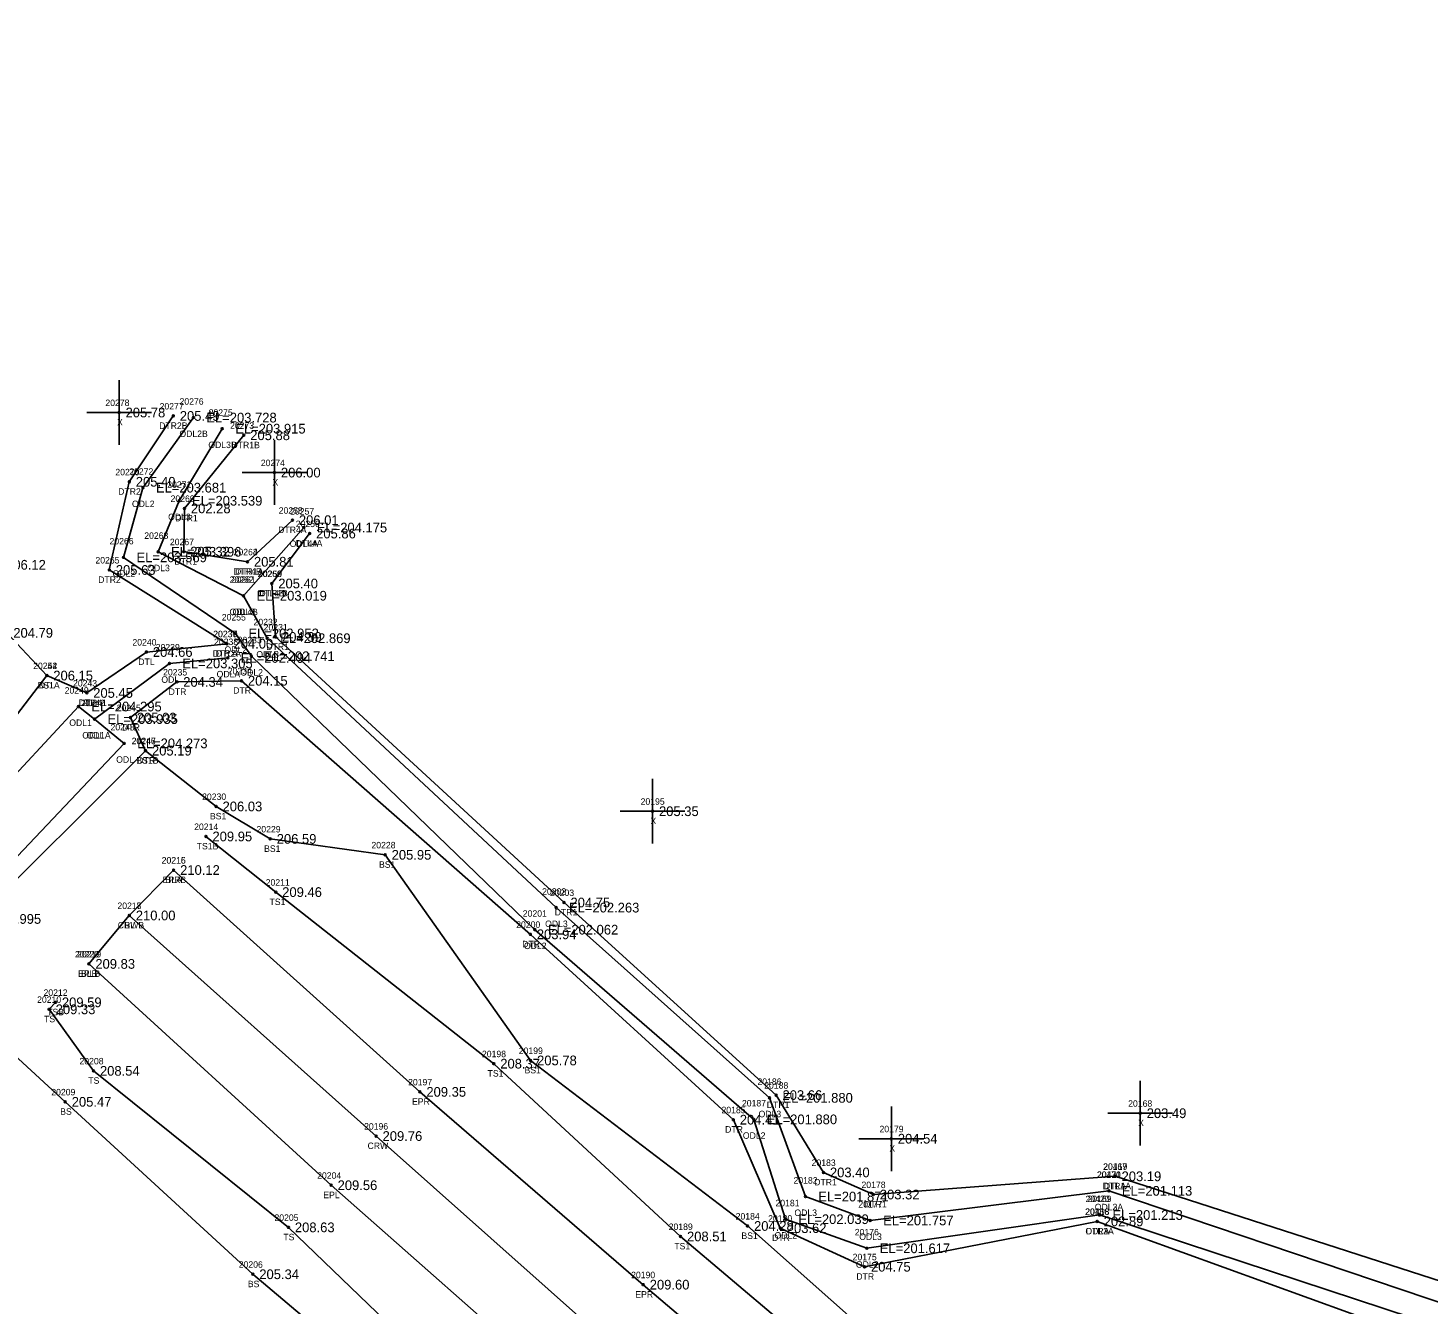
# Model space of a CAD drawing. Extents: x 2260230 to 2261304, y 1064626 to 1065587.
# Drawn here: x 2260481.3 to 2260697.7, y 1065283.6 to 1065480.8 of the extents above; entities that cross this region are included whole.
import ezdxf

# ---------------------------------------------------------------- set-up
doc = ezdxf.new("R2010")
doc.units = 0
for name, color, linetype in [('RD_DTM_BkLn1', 7, 'Continuous'), ('RD_DTM_BkLn2', 7, 'Continuous'), ('RD_DTM_BkLn_txCode', 7, 'Continuous'), ('RD_EX_H2O', 7, 'Continuous'), ('RD_EX_H2O_txCode', 7, 'Continuous'), ('RD_EX_Misc', 7, 'Continuous'), ('RD_EX_Misc_txCode', 7, 'Continuous'), ('RD_EX_Road', 7, 'Continuous'), ('RD_EX_Road_txCode', 7, 'Continuous'), ('RD_EX_TX_H2O_ELEV', 7, 'Continuous'), ('RD_EX_TX_Misc_ELEV', 7, 'Continuous'), ('RD_EX_TX_Road_ELEV', 7, 'Continuous'), ('RD_HC_Survey_ELEV', 7, 'Continuous'), ('RD_HC_Survey_txCode', 7, 'Continuous'), ('RD_SMD_Locator', 7, 'Continuous')]:
    doc.layers.add(name, color=color, linetype=linetype)

msp = doc.modelspace()

# ---------------------------------------------------------------- linework, layer by layer
at = {"layer": 'RD_DTM_BkLn1'}
for points in [[(2260503.82, 1065350.69), (2260496.97, 1065343.67), (2260490.72, 1065336.18)], [(2260779.46, 1065104.44), (2260742.48, 1065135.39), (2260673.31, 1065192.46), (2260608.04, 1065246.07), (2260570.56, 1065278.04), (2260535.11, 1065309.57), (2260496.97, 1065343.67)]]:
    msp.add_lwpolyline(points, dxfattribs=at)
at = {"layer": 'RD_DTM_BkLn2'}
for points in [[(2260484.22, 1065380.75), (2260478.04, 1065387.35), (2260476.93, 1065397.87), (2260411.32, 1065463.45), (2260400.24, 1065480.84)], [(2260803.42, 1065119.58), (2260791.14, 1065121.96), (2260758.99, 1065152.43), (2260688.43, 1065210.53), (2260677.06, 1065221.37), (2260674.34, 1065224.52), (2260669.99, 1065225.64), (2260624.69, 1065267.1), (2260592.52, 1065295.67), (2260558.99, 1065321.26), (2260536.51, 1065353.04), (2260518.75, 1065355.5), (2260510.38, 1065360.52), (2260499.47, 1065369.14)], [(2260788.43, 1065115.1), (2260756.25, 1065149.85), (2260685.54, 1065207.45), (2260620.51, 1065261.6), (2260582.16, 1065294.05), (2260553.3, 1065320.76), (2260519.6, 1065347.28), (2260508.82, 1065355.88)], [(2260769.94, 1065084.22), (2260759.25, 1065090.93), (2260723.51, 1065114.68), (2260656.37, 1065173.06), (2260640.88, 1065186.75), (2260590.19, 1065225.63), (2260553.18, 1065256.82), (2260516.06, 1065288.21), (2260487.07, 1065314.86), (2260465.96, 1065334.21)], [(2260770.13, 1065093.5), (2260766.75, 1065094.76), (2260758.85, 1065096.78), (2260743.23, 1065112.86), (2260730.88, 1065117.95), (2260648.47, 1065190.67), (2260642.26, 1065193.52), (2260595.88, 1065231.39), (2260557.16, 1065261.19), (2260521.56, 1065295.46), (2260491.43, 1065319.65), (2260484.59, 1065329.16), (2260485.55, 1065330.24)]]:
    msp.add_lwpolyline(points, dxfattribs=at)
at = {"layer": 'RD_EX_H2O'}
for p, q in [((2260522.18, 1065404.77), (2260515.23, 1065398.34)), ((2260523.94, 1065403.63), (2260514.62, 1065393.09)), ((2260524.84, 1065402.7), (2260518.99, 1065394.98))]:
    msp.add_line(p, q, dxfattribs=at)
for points in [[(2260512.07, 1065385.67), (2260493.88, 1065397.07), (2260496.97, 1065410.7), (2260503.77, 1065420.88)], [(2260646.91, 1065297.37), (2260610.95, 1065292.22), (2260598.38, 1065296.72), (2260593.48, 1065312.15), (2260559.66, 1065341.47), (2260515.83, 1065383.74), (2260513.38, 1065387.26), (2260496.08, 1065399.02), (2260499.08, 1065409.79), (2260506.87, 1065420.62)], [(2260648.37, 1065301.1), (2260611.48, 1065296.52), (2260601.45, 1065300.22), (2260595.91, 1065315.48), (2260562.92, 1065344.88), (2260518.29, 1065386.52), (2260514.62, 1065393.09), (2260501.42, 1065399.88), (2260504.66, 1065407.77), (2260511.34, 1065418.91)], [(2260515.23, 1065398.34), (2260505.38, 1065399.9), (2260505.49, 1065406.59), (2260514.66, 1065417.89)], [(2260649.32, 1065303.35), (2260611.96, 1065300.53), (2260604.25, 1065303.95), (2260596.92, 1065315.9), (2260564.15, 1065345.67), (2260519.57, 1065386.72), (2260518.99, 1065394.98)], [(2260512.07, 1065385.67), (2260499.61, 1065384.39), (2260490.39, 1065378.06), (2260484.22, 1065380.75), (2260461.06, 1065350.52), (2260459.63, 1065339.19), (2260447.16, 1065331.46), (2260428.77, 1065320.54)], [(2260512.19, 1065383.47), (2260503.16, 1065382.63), (2260491.6, 1065374.02), (2260496.18, 1065370.27), (2260470.47, 1065343.13), (2260465.09, 1065335.21), (2260448.41, 1065329.85), (2260430.6, 1065317.94)], [(2260646.56, 1065296.38), (2260610.59, 1065289.37), (2260597.58, 1065295.34), (2260590.32, 1065312.1), (2260558.95, 1065340.75), (2260514.3, 1065379.95), (2260504.3, 1065379.76), (2260497.13, 1065374.25), (2260499.47, 1065369.14), (2260472.37, 1065342.14), (2260468.09, 1065337.19), (2260465.96, 1065334.21), (2260450.6, 1065327.87), (2260431.86, 1065315.1)], [(2260491.6, 1065374.02), (2260489.1, 1065375.96), (2260466.13, 1065351.23), (2260467.67, 1065345), (2260461.29, 1065337.12), (2260448.41, 1065329.85)], [(2260649.32, 1065303.35), (2260742.36, 1065273.33), (2260794.49, 1065236.41), (2260847.14, 1065213.75), (2260856.6, 1065227.36), (2260843.65, 1065244.12)], [(2260648.37, 1065301.1), (2260738.72, 1065270.62), (2260793.11, 1065233.68), (2260850.51, 1065208.71), (2260885.55, 1065179.82)], [(2260646.91, 1065297.37), (2260734.94, 1065268.39), (2260788.77, 1065229.77), (2260848.02, 1065204.23), (2260881.52, 1065170.81)], [(2260646.56, 1065296.38), (2260731.62, 1065265.57), (2260787.15, 1065228.1), (2260847.76, 1065200.44), (2260874.83, 1065172.21)]]:
    msp.add_lwpolyline(points, dxfattribs=at)
at = {"layer": 'RD_EX_Misc'}
for p, q in [((2260495.39, 1065416.41), (2260495.39, 1065426.41)), ((2260490.39, 1065421.41), (2260500.39, 1065421.41)), ((2260519.4, 1065407.12), (2260519.4, 1065417.12)), ((2260514.4, 1065412.12), (2260524.4, 1065412.12)), ((2260577.83, 1065354.78), (2260577.83, 1065364.78)), ((2260572.83, 1065359.78), (2260582.83, 1065359.78)), ((2260653.2, 1065308.1), (2260653.2, 1065318.1)), ((2260614.74, 1065304.16), (2260614.74, 1065314.16)), ((2260648.2, 1065313.1), (2260658.2, 1065313.1)), ((2260609.74, 1065309.16), (2260619.74, 1065309.16))]:
    msp.add_line(p, q, dxfattribs=at)
at = {"layer": 'RD_EX_Road'}
for points in [[(2260785.94, 1065112.1), (2260748.83, 1065143.25), (2260679.89, 1065200.15), (2260614.93, 1065253.84), (2260576.4, 1065286.6), (2260541.88, 1065316.4), (2260503.82, 1065350.69)], [(2260773.44, 1065097.37), (2260736.13, 1065128.07), (2260602.8, 1065238.77), (2260563.77, 1065270.54), (2260528.16, 1065301.97), (2260490.72, 1065336.18)]]:
    msp.add_lwpolyline(points, dxfattribs=at)
at = {"layer": 'RD_SMD_Locator'}
for centre in [(2260495.39, 1065421.41), (2260503.77, 1065420.88), (2260506.87, 1065420.62), (2260511.34, 1065418.91), (2260514.66, 1065417.89), (2260519.4, 1065412.12), (2260496.97, 1065410.7), (2260499.08, 1065409.79), (2260504.66, 1065407.77), (2260505.49, 1065406.59), (2260522.18, 1065404.77), (2260523.94, 1065403.63), (2260524.84, 1065402.7), (2260496.08, 1065399.02), (2260501.42, 1065399.88), (2260505.38, 1065399.9), (2260515.23, 1065398.34), (2260515.23, 1065398.34), (2260493.88, 1065397.07), (2260518.99, 1065394.98), (2260518.99, 1065394.98), (2260514.62, 1065393.09), (2260514.62, 1065393.09), (2260512.07, 1065385.67), (2260512.07, 1065385.67), (2260513.38, 1065387.26), (2260518.29, 1065386.52), (2260519.57, 1065386.72), (2260499.61, 1065384.39), (2260512.19, 1065383.47), (2260515.83, 1065383.74), (2260503.16, 1065382.63), (2260484.22, 1065380.75), (2260484.22, 1065380.75), (2260504.3, 1065379.76), (2260514.3, 1065379.95), (2260490.39, 1065378.06), (2260489.1, 1065375.96), (2260491.6, 1065374.02), (2260491.6, 1065374.02), (2260497.13, 1065374.25), (2260496.18, 1065370.27), (2260499.47, 1065369.14), (2260499.47, 1065369.14), (2260510.38, 1065360.52), (2260577.83, 1065359.78), (2260508.82, 1065355.88), (2260518.75, 1065355.5), (2260536.51, 1065353.04), (2260503.82, 1065350.69), (2260503.82, 1065350.69), (2260519.6, 1065347.28), (2260562.92, 1065344.88), (2260564.15, 1065345.67), (2260496.97, 1065343.67), (2260496.97, 1065343.67), (2260558.95, 1065340.75), (2260559.66, 1065341.47), (2260490.72, 1065336.18), (2260490.72, 1065336.18), (2260484.59, 1065329.16), (2260485.55, 1065330.24), (2260553.3, 1065320.76), (2260558.99, 1065321.26), (2260491.43, 1065319.65), (2260541.88, 1065316.4), (2260596.92, 1065315.9), (2260487.07, 1065314.86), (2260595.91, 1065315.48), (2260590.32, 1065312.1), (2260593.48, 1065312.15), (2260653.2, 1065313.1), (2260535.11, 1065309.57), (2260614.74, 1065309.16), (2260604.25, 1065303.95), (2260649.32, 1065303.35), (2260649.32, 1065303.35), (2260528.16, 1065301.97), (2260648.37, 1065301.1), (2260648.37, 1065301.1), (2260601.45, 1065300.22), (2260611.96, 1065300.53), (2260598.38, 1065296.72), (2260611.48, 1065296.52), (2260646.91, 1065297.37), (2260646.91, 1065297.37), (2260521.56, 1065295.46), (2260592.52, 1065295.67), (2260597.58, 1065295.34), (2260646.56, 1065296.38), (2260646.56, 1065296.38), (2260582.16, 1065294.05), (2260610.95, 1065292.22), (2260516.06, 1065288.21), (2260610.59, 1065289.37), (2260576.4, 1065286.6)]:
    msp.add_circle(centre, 0.15, dxfattribs=at)

# ---------------------------------------------------------------- texts
at = {"layer": 'RD_DTM_BkLn_txCode'}
for s, p in [('20252', (2260482.11, 1065381.75)), ('BS1A', (2260482.79, 1065378.75)), ('20247', (2260497.35, 1065370.14)), ('BS1B', (2260498.05, 1065367.14)), ('20230', (2260508.22, 1065361.52)), ('BS1', (2260509.43, 1065358.52)), ('20214', (2260506.99, 1065356.88)), ('20229', (2260516.63, 1065356.5)), ('20228', (2260534.39, 1065354.04)), ('TS1B', (2260507.39, 1065353.88)), ('BS1', (2260517.8, 1065353.5)), ('20216', (2260501.96, 1065351.69)), ('BS1', (2260535.56, 1065351.04)), ('BLA', (2260502.57, 1065348.69)), ('20211', (2260518.05, 1065348.28)), ('20217', (2260495.13, 1065344.67)), ('TS1', (2260518.64, 1065345.28)), ('BL', (2260496.21, 1065341.67)), ('20219', (2260488.89, 1065337.18)), ('BLB', (2260489.5, 1065334.18)), ('20212', (2260483.71, 1065331.24)), ('20210', (2260482.72, 1065330.16)), ('TSB', (2260484.28, 1065328.24)), ('TS', (2260483.8, 1065327.16)), ('20198', (2260551.47, 1065321.76)), ('20199', (2260557.16, 1065322.26)), ('20208', (2260489.27, 1065320.65)), ('TS', (2260490.63, 1065317.65)), ('TS1', (2260552.34, 1065318.76)), ('BS1', (2260558.05, 1065319.26)), ('20209', (2260484.91, 1065315.86)), ('BS', (2260486.29, 1065312.86)), ('20205', (2260519.4, 1065296.46)), ('20184', (2260590.68, 1065296.67)), ('TS', (2260520.77, 1065293.46)), ('20189', (2260580.33, 1065295.05)), ('BS1', (2260591.57, 1065293.67)), ('TS1', (2260581.2, 1065292.05)), ('20206', (2260513.88, 1065289.21)), ('BS', (2260515.28, 1065286.21))]:
    msp.add_text(s, height=1, dxfattribs=at).set_placement(p)
at = {"layer": 'RD_EX_H2O_txCode'}
for s, p in [('20277', (2260501.65, 1065421.88)), ('20276', (2260504.73, 1065422.62)), ('20275', (2260509.23, 1065420.91)), ('DTR2B', (2260501.58, 1065418.88)), ('ODL2B', (2260504.71, 1065417.62)), ('20273', (2260512.54, 1065418.89)), ('ODL3B', (2260509.18, 1065415.91)), ('DTR1B', (2260512.76, 1065415.89)), ('20270', (2260494.81, 1065411.7)), ('20272', (2260496.96, 1065411.79)), ('DTR2', (2260495.25, 1065408.7)), ('20271', (2260502.83, 1065409.77)), ('ODL2', (2260497.38, 1065406.79)), ('20269', (2260503.35, 1065407.59)), ('ODL3', (2260502.97, 1065404.77)), ('DTR1', (2260504.06, 1065404.59)), ('20258', (2260520.06, 1065405.77)), ('20257', (2260521.82, 1065405.63)), ('20268', (2260499.28, 1065401.88)), ('DTR4A', (2260519.98, 1065402.77)), ('20256', (2260522.69, 1065403.7)), ('20266', (2260493.91, 1065401.02)), ('20267', (2260503.24, 1065400.9)), ('ODL4A', (2260521.76, 1065400.63)), ('DTL4A', (2260522.65, 1065400.7)), ('20265', (2260491.73, 1065398.07)), ('DTR1', (2260503.94, 1065397.9)), ('20263', (2260513.09, 1065399.34)), ('20264', (2260513.09, 1065399.34)), ('ODL2', (2260494.38, 1065396.02)), ('ODL3', (2260499.73, 1065396.88)), ('20262', (2260512.48, 1065395.09)), ('20261', (2260512.76, 1065395.09)), ('DTR4B', (2260513.04, 1065396.34)), ('DTR1A', (2260513.31, 1065396.34)), ('20260', (2260516.81, 1065395.98)), ('20259', (2260516.87, 1065395.98)), ('DTR2', (2260492.16, 1065395.07)), ('DTL4B', (2260516.82, 1065392.98)), ('DTR1B', (2260517.08, 1065392.98)), ('20255', (2260511.26, 1065389.26)), ('ODL4B', (2260512.46, 1065390.09)), ('ODL3', (2260512.93, 1065390.09)), ('20236', (2260509.92, 1065386.67)), ('20237', (2260509.95, 1065386.67)), ('20232', (2260516.17, 1065388.52)), ('20231', (2260517.73, 1065387.72)), ('20240', (2260497.45, 1065385.39)), ('20239', (2260501.05, 1065384.63)), ('20238', (2260510.07, 1065385.47)), ('20233', (2260513.71, 1065385.74)), ('DTR1', (2260518.14, 1065384.72)), ('DTL', (2260498.36, 1065382.39)), ('DTR2A', (2260509.86, 1065383.67)), ('DTLA', (2260510.33, 1065383.67)), ('ODL2', (2260511.68, 1065384.26)), ('ODL3', (2260516.6, 1065383.52)), ('20244', (2260482.11, 1065381.75)), ('20235', (2260502.19, 1065380.76)), ('ODLA', (2260510.46, 1065380.47)), ('20234', (2260512.18, 1065380.95)), ('ODL2', (2260514.13, 1065380.74)), ('DTL', (2260482.98, 1065378.75)), ('20249', (2260486.98, 1065377.96)), ('20243', (2260488.27, 1065379.06)), ('ODL', (2260501.92, 1065379.63)), ('DTR', (2260513.03, 1065377.95)), ('DTL', (2260489.15, 1065376.06)), ('20242', (2260489.48, 1065376.02)), ('20241', (2260489.77, 1065376.02)), ('DTR', (2260503.04, 1065377.76)), ('20245', (2260495.01, 1065375.25)), ('ODL1', (2260487.69, 1065372.96)), ('20248', (2260494.07, 1065372.27)), ('DTR', (2260495.86, 1065372.25)), ('ODL1A', (2260489.7, 1065371.02)), ('ODL', (2260490.36, 1065371.02)), ('20246', (2260497.32, 1065370.14)), ('ODL', (2260494.94, 1065367.27)), ('DTR', (2260498.2, 1065367.14)), ('20202', (2260560.77, 1065346.88)), ('20203', (2260561.99, 1065346.67)), ('20201', (2260557.78, 1065343.47)), ('DTR1', (2260562.71, 1065343.67)), ('20200', (2260556.76, 1065341.75)), ('ODL3', (2260561.23, 1065341.88)), ('DTR', (2260557.69, 1065338.75)), ('ODL2', (2260557.96, 1065338.47)), ('20186', (2260594.05, 1065317.48)), ('20188', (2260595.09, 1065316.9)), ('20185', (2260588.49, 1065313.1)), ('20187', (2260591.65, 1065314.15)), ('DTR1', (2260595.49, 1065313.9)), ('ODL3', (2260594.22, 1065312.48)), ('DTR', (2260589.05, 1065310.1)), ('ODL2', (2260591.79, 1065309.15)), ('20183', (2260602.42, 1065304.95)), ('20167', (2260647.46, 1065304.35)), ('20419', (2260647.49, 1065304.35)), ('20182', (2260599.62, 1065302.22)), ('20170', (2260646.49, 1065303.1)), ('20421', (2260646.53, 1065303.1)), ('DTR1', (2260602.82, 1065301.95)), ('20178', (2260610.13, 1065301.53)), ('DTR1A', (2260647.4, 1065301.35)), ('DTLA', (2260647.59, 1065301.35)), ('20181', (2260596.83, 1065298.72)), ('20177', (2260609.64, 1065298.52)), ('DTR1', (2260610.53, 1065298.53)), ('20420', (2260644.76, 1065299.37)), ('20169', (2260645.05, 1065299.37)), ('ODL3A', (2260646.18, 1065298.1)), ('ODL2A', (2260646.18, 1065298.1)), ('20180', (2260595.7, 1065296.34)), ('ODL3', (2260599.76, 1065297.22)), ('20166', (2260644.67, 1065297.38)), ('20418', (2260644.72, 1065297.38)), ('ODL2', (2260596.69, 1065293.72)), ('20176', (2260609.09, 1065294.22)), ('ODL3', (2260609.78, 1065293.52)), ('ODL2A', (2260644.73, 1065294.37)), ('ODL3A', (2260644.73, 1065294.37)), ('DTRA', (2260644.8, 1065294.38)), ('DTRA', (2260644.8, 1065294.38)), ('DTR', (2260596.31, 1065293.34)), ('20175', (2260608.76, 1065290.37)), ('ODL2', (2260609.26, 1065289.22)), ('DTR', (2260609.33, 1065287.37))]:
    msp.add_text(s, height=1, dxfattribs=at).set_placement(p)
at = {"layer": 'RD_EX_Misc_txCode'}
for s, p in [('20278', (2260493.27, 1065422.41)), ('X', (2260495.08, 1065419.41)), ('20274', (2260517.29, 1065413.12)), ('X', (2260519.09, 1065410.12)), ('20195', (2260575.99, 1065360.78)), ('X', (2260577.51, 1065357.78)), ('20168', (2260651.34, 1065314.1)), ('X', (2260652.88, 1065311.1)), ('20179', (2260612.91, 1065310.16)), ('X', (2260614.43, 1065307.16))]:
    msp.add_text(s, height=1, dxfattribs=at).set_placement(p)
at = {"layer": 'RD_EX_Road_txCode'}
for s, p in [('20215', (2260501.98, 1065351.69)), ('EPRB', (2260502.12, 1065348.69)), ('20220', (2260488.57, 1065337.18)), ('EPLB', (2260489.05, 1065334.18)), ('20197', (2260540.05, 1065317.4)), ('EPR', (2260540.66, 1065314.4)), ('20204', (2260526, 1065302.97)), ('EPL', (2260526.95, 1065299.97)), ('20190', (2260574.52, 1065287.6)), ('EPR', (2260575.17, 1065284.6))]:
    msp.add_text(s, height=1, dxfattribs=at).set_placement(p)
at = {"layer": 'RD_EX_TX_H2O_ELEV'}
for s, p in [('205.49', (2260504.77, 1065420.13)), ('EL=203.728', (2260508.87, 1065419.87)), ('EL=203.915', (2260513.34, 1065418.16)), ('205.88', (2260515.66, 1065417.14)), ('205.40', (2260497.97, 1065409.95)), ('EL=203.681', (2260501.08, 1065409.04)), ('202.28', (2260506.49, 1065405.84)), ('EL=203.539', (2260506.66, 1065407.02)), ('206.01', (2260523.18, 1065404.02)), ('205.86', (2260525.84, 1065401.95)), ('EL=204.175', (2260525.94, 1065402.88)), ('EL=203.396', (2260503.42, 1065399.13)), ('205.32', (2260506.38, 1065399.15)), ('EL=203.569', (2260498.08, 1065398.27)), ('205.81', (2260516.23, 1065397.59)), ('205.81', (2260516.23, 1065397.59)), ('205.63', (2260494.88, 1065396.32)), ('205.40', (2260519.99, 1065394.23)), ('205.40', (2260519.99, 1065394.23)), ('EL=203.019', (2260516.62, 1065392.34)), ('EL=203.019', (2260516.62, 1065392.34)), ('EL=202.952', (2260515.38, 1065386.51)), ('204.39', (2260520.57, 1065385.97)), ('204.00', (2260513.07, 1065384.92)), ('204.00', (2260513.07, 1065384.92)), ('EL=202.869', (2260520.29, 1065385.77)), ('204.66', (2260500.61, 1065383.64)), ('EL=203.305', (2260505.16, 1065381.88)), ('EL=202.494', (2260514.19, 1065382.72)), ('EL=202.741', (2260517.83, 1065382.99)), ('206.15', (2260485.22, 1065380)), ('205.45', (2260491.39, 1065377.31)), ('204.34', (2260505.3, 1065379.01)), ('204.15', (2260515.3, 1065379.2)), ('EL=204.295', (2260491.1, 1065375.21)), ('EL=203.935', (2260493.6, 1065373.27)), ('EL=203.935', (2260493.6, 1065373.27)), ('205.03', (2260498.13, 1065373.5)), ('EL=204.273', (2260498.18, 1065369.52)), ('205.19', (2260500.47, 1065368.39)), ('204.75', (2260565.15, 1065344.92)), ('EL=202.263', (2260564.92, 1065344.13)), ('EL=203.995', (2260472.47, 1065342.38)), ('EL=202.062', (2260561.66, 1065340.72)), ('203.94', (2260559.95, 1065340)), ('203.66', (2260597.92, 1065315.15)), ('EL=201.880', (2260597.91, 1065314.73)), ('204.41', (2260591.32, 1065311.35)), ('EL=201.880', (2260595.48, 1065311.4)), ('203.40', (2260605.25, 1065303.2)), ('203.19', (2260650.32, 1065302.6)), ('203.19', (2260650.32, 1065302.6)), ('EL=201.871', (2260603.45, 1065299.47)), ('203.32', (2260612.96, 1065299.78)), ('EL=201.113', (2260650.37, 1065300.35)), ('EL=201.113', (2260650.37, 1065300.35)), ('EL=202.039', (2260600.38, 1065295.97)), ('EL=201.757', (2260613.48, 1065295.77)), ('202.89', (2260647.56, 1065295.63)), ('202.89', (2260647.56, 1065295.63)), ('EL=201.213', (2260648.91, 1065296.62)), ('EL=201.213', (2260648.91, 1065296.62)), ('203.62', (2260598.58, 1065294.59)), ('EL=201.617', (2260612.95, 1065291.47)), ('204.75', (2260611.59, 1065288.62))]:
    msp.add_text(s, height=1.5, dxfattribs=at).set_placement(p)
at = {"layer": 'RD_EX_TX_Misc_ELEV'}
for s, p in [('205.78', (2260496.39, 1065420.66)), ('206.00', (2260520.4, 1065411.37)), ('206.12', (2260477.93, 1065397.12)), ('204.79', (2260479.04, 1065386.6)), ('206.15', (2260485.22, 1065380)), ('205.19', (2260500.47, 1065368.39)), ('206.03', (2260511.38, 1065359.77)), ('205.35', (2260578.83, 1065359.03)), ('209.95', (2260509.82, 1065355.13)), ('206.59', (2260519.75, 1065354.75)), ('205.95', (2260537.51, 1065352.29)), ('210.12', (2260504.82, 1065349.94)), ('209.46', (2260520.6, 1065346.53)), ('210.00', (2260497.97, 1065342.92)), ('209.83', (2260491.72, 1065335.43)), ('209.33', (2260485.59, 1065328.41)), ('209.59', (2260486.55, 1065329.49)), ('208.54', (2260492.43, 1065318.9)), ('208.37', (2260554.3, 1065320.01)), ('205.78', (2260559.99, 1065320.51)), ('205.47', (2260488.07, 1065314.11)), ('203.49', (2260654.2, 1065312.35)), ('204.54', (2260615.74, 1065308.41)), ('208.63', (2260522.56, 1065294.71)), ('208.51', (2260583.16, 1065293.3)), ('204.28', (2260593.52, 1065294.92)), ('205.34', (2260517.06, 1065287.46))]:
    msp.add_text(s, height=1.5, dxfattribs=at).set_placement(p)
at = {"layer": 'RD_EX_TX_Road_ELEV'}
for s, p in [('210.12', (2260504.82, 1065349.94)), ('209.83', (2260491.72, 1065335.43)), ('209.35', (2260542.88, 1065315.65)), ('209.56', (2260529.16, 1065301.22)), ('209.60', (2260577.4, 1065285.85))]:
    msp.add_text(s, height=1.5, dxfattribs=at).set_placement(p)
at = {"layer": 'RD_HC_Survey_ELEV'}
for s, p in [('210.00', (2260497.97, 1065342.92)), ('209.76', (2260536.11, 1065308.82))]:
    msp.add_text(s, height=1.5, dxfattribs=at).set_placement(p)
at = {"layer": 'RD_HC_Survey_txCode'}
for s, p in [('20218', (2260495.13, 1065344.67)), ('CRWB', (2260495.18, 1065341.67)), ('20196', (2260533.25, 1065310.57)), ('CRW', (2260533.79, 1065307.57))]:
    msp.add_text(s, height=1, dxfattribs=at).set_placement(p)

doc.saveas('drawing.dxf')
